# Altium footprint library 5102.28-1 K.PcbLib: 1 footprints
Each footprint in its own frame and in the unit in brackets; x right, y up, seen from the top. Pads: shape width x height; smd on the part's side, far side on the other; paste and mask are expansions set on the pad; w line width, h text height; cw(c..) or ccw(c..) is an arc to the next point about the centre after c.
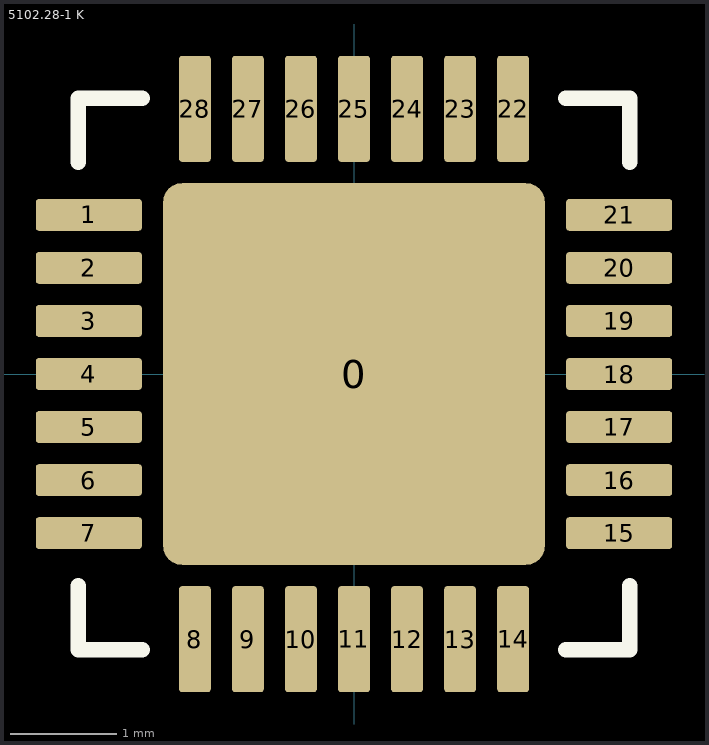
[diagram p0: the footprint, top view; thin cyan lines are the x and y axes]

## 5102.28-1 K [mm]
pads (29):
  rrect10% 3.6x3.6 smd: 0(0,0)
  rrect20% 1x0.3 smd: 1(-2.5,1.5) 2(-2.5,1) 3(-2.5,0.5) 4(-2.5,0) 5(-2.5,-0.5) 6(-2.5,-1) 7(-2.5,-1.5) 15(2.5,-1.5) 16(2.5,-1) 17(2.5,-0.5) 18(2.5,0) 19(2.5,0.5) 20(2.5,1) 21(2.5,1.5)
  rrect20% 0.3x1 smd: 8(-1.5,-2.5) 9(-1,-2.5) 10(-0.5,-2.5) 11(0,-2.5) 12(0.5,-2.5) 13(1,-2.5) 14(1.5,-2.5) 22(1.5,2.5) 23(1,2.5) 24(0.5,2.5) 25(0,2.5) 26(-0.5,2.5) 27(-1,2.5) 28(-1.5,2.5)
Top Overlay:
  lines w0.15: -2.6,-2 -2.6,-2.6 -2,-2.6 ; -2.6,2 -2.6,2.6 -2,2.6 ; 2,-2.6 2.6,-2.6 2.6,-2 ; 2,2.6 2.6,2.6 2.6,2
  text "." at -3.72,1.785 h5
3D body "QFN-28-1EP_5x5mm_P0.5mm_EP3.35x3.35mm.step": height 0.92, standoff 0, extent -2.5,-2.5 2.5,2.5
